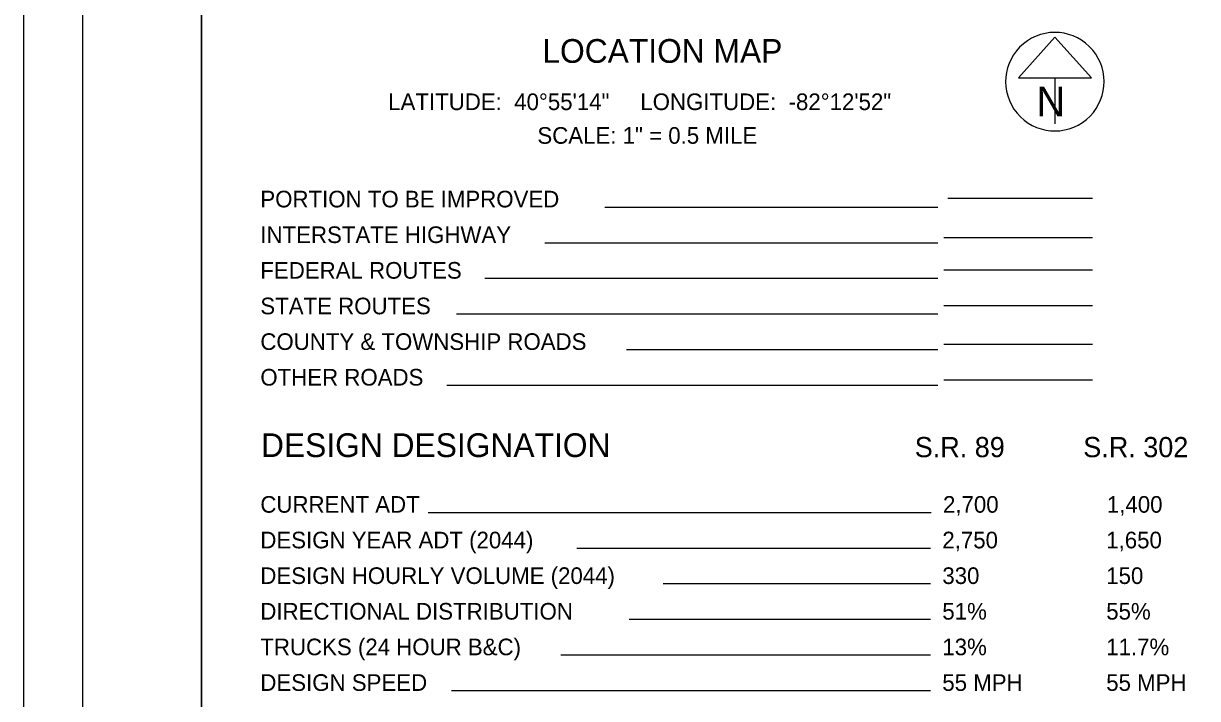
# Model space of a CAD drawing. Extents: x 0 to 72, y -85 to 22.
# Drawn here: x 0 to 9.89, y 8.24 to 13.93 of the extents above; entities that cross this region are included whole.
import ezdxf

# ---------------------------------------------------------------- set-up
doc = ezdxf.new("R2010")
doc.units = 0
for name, color, linetype in [('GM_X_Adjacent_County', 7, 'Continuous'), ('GM_X_County', 7, 'Continuous'), ('GM_X_Section', 7, 'Continuous'), ('GM_X_Township', 7, 'Continuous')]:
    doc.layers.add(name, color=color, linetype=linetype)

msp = doc.modelspace()

# ---------------------------------------------------------------- linework, layer by layer
at = {"layer": 'GM_X_County'}
for points in [[(0.5, 21.5), (1.5, 21.5), (1.5, 0.5), (0.5, 0.5)], [(1.5, 21.5), (33.5, 21.5), (33.5, 0.5), (1.5, 0.5)]]:
    msp.add_lwpolyline(points, close=True, dxfattribs=at)
at = {"layer": 'GM_X_Section'}
msp.add_lwpolyline([(0, 0), (34, 0), (34, 22), (0, 22)], close=True, dxfattribs=at)
at = {"layer": 'GM_X_Township'}
for p, q in [((8.6845, 13.8091), (8.3769, 13.4678)), ((8.9921, 13.4678), (8.6845, 13.8091)), ((8.3769, 13.4678), (8.9921, 13.4678)), ((8.6845, 13.4678), (8.6845, 13.0811)), ((8.6845, 13.4353), (8.6845, 13.4353)), ((8.6845, 13.4353), (8.6845, 13.4353)), ((7.7, 12.3767), (4.8937, 12.3767)), ((7.7827, 12.4553), (9, 12.4553)), ((7.7, 12.0767), (4.3895, 12.0767)), ((9, 12.1207), (7.75, 12.1207)), ((7.7, 11.7767), (3.8854, 11.7767)), ((9, 11.8491), (7.75, 11.8491)), ((7.7, 11.4767), (3.6448, 11.4767)), ((9, 11.5491), (7.75, 11.5491)), ((7.7, 11.1767), (5.0782, 11.1767)), ((9, 11.2223), (7.75, 11.2223)), ((7.7, 10.8767), (3.5657, 10.8767)), ((9, 10.9223), (7.75, 10.9223)), ((7.6424, 9.8062), (3.4085, 9.8062)), ((7.6368, 9.5062), (4.6592, 9.5062)), ((7.6368, 9.2062), (5.3852, 9.2062)), ((7.6368, 8.9062), (5.0988, 8.9062)), ((7.6368, 8.6062), (4.5259, 8.6062)), ((7.6368, 8.3062), (3.6035, 8.3062))]:
    msp.add_line(p, q, dxfattribs=at)
msp.add_arc((8.6845, 13.4353), 0.4148, 129.77984, 129.76332, dxfattribs=at)

# ---------------------------------------------------------------- texts
at = {"layer": 'GM_X_Adjacent_County'}
for s, height, p in [('LOCATION MAP', 0.2, (4.3691, 13.5938)), ('LATITUDE:  40°55\'14"     LONGITUDE:  -82°12\'52"', 0.14, (3.071, 13.1959)), ('SCALE: 1" = 0.5 MILE', 0.14, (4.3272, 12.9124)), ('PORTION TO BE IMPROVED', 0.14, (1.9944, 12.3767)), ('INTERSTATE HIGHWAY', 0.14, (1.9944, 12.0767)), ('FEDERAL ROUTES', 0.14, (1.9944, 11.7767)), ('STATE ROUTES', 0.14, (1.9944, 11.4767)), ('COUNTY & TOWNSHIP ROADS', 0.14, (1.9944, 11.1767)), ('OTHER ROADS', 0.14, (1.9944, 10.8767)), ('CURRENT ADT', 0.14, (1.9944, 9.8062)), ('2,700', 0.14, (7.7424, 9.8062)), ('     1,400', 0.14, (8.8624, 9.8062)), ('DESIGN YEAR ADT (2044)', 0.14, (1.9944, 9.5062)), ('2,750', 0.14, (7.7368, 9.5062)), ('     1,650', 0.14, (8.8568, 9.5062)), ('DESIGN HOURLY VOLUME (2044)', 0.14, (1.9944, 9.2062)), ('330', 0.14, (7.7368, 9.2062)), ('     150', 0.14, (8.8568, 9.2062)), ('DIRECTIONAL DISTRIBUTION', 0.14, (1.9944, 8.9062)), ('51%', 0.14, (7.7368, 8.9062)), ('     55%', 0.14, (8.8568, 8.9062)), ('TRUCKS (24 HOUR B&C)', 0.14, (1.9944, 8.6062)), ('13%', 0.14, (7.7368, 8.6062)), ('     11.7%', 0.14, (8.8568, 8.6062)), ('DESIGN SPEED', 0.14, (1.9944, 8.3062)), ('55 MPH', 0.14, (7.7368, 8.3062)), ('     55 MPH', 0.14, (8.8568, 8.3062))]:
    msp.add_text(s, height=height, dxfattribs=at).set_placement(p)
at = {"layer": 'GM_X_Township'}
for s, height, p in [('N', 0.25, (8.5292, 13.144)), ('DESIGN DESIGNATION', 0.2, (2, 10.2747)), ('S.R. 89', 0.17, (7.5047, 10.2736)), ('S.R. 302', 0.17, (8.9236, 10.2736))]:
    msp.add_text(s, height=height, dxfattribs=at).set_placement(p)

doc.saveas('drawing.dxf')
